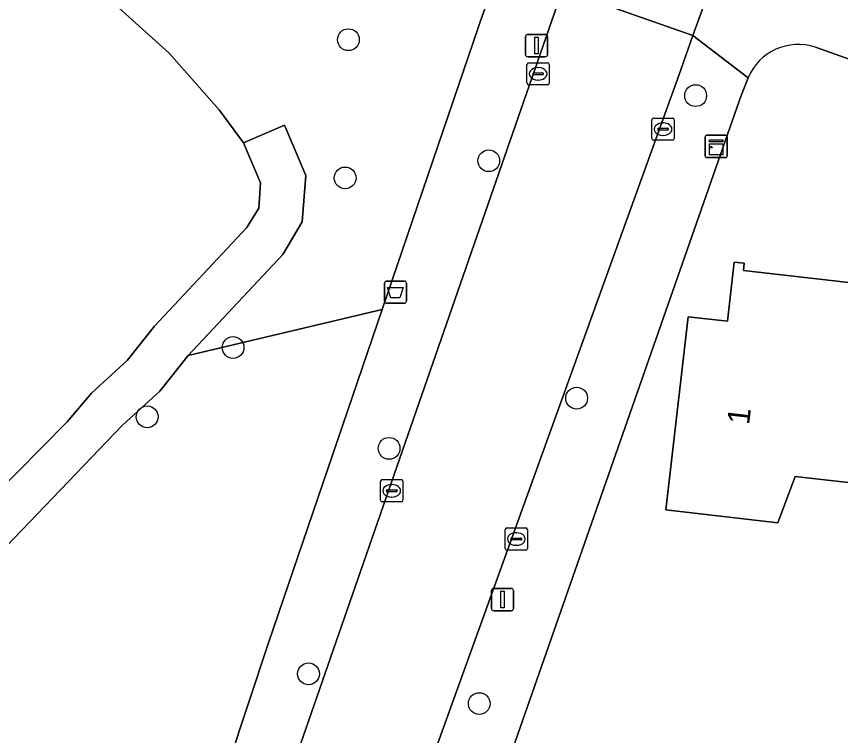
# Model space of a CAD drawing. Extents: x 162396 to 163643, y 386452 to 387406.
# Drawn here: x 162508.79 to 162545.79, y 386600.76 to 386633.03 of the extents above; entities that cross this region are included whole.
import ezdxf

# ---------------------------------------------------------------- set-up
doc = ezdxf.new("R2010")
doc.units = 0
for name, color, linetype in [('IMGEO_Afvalbak', 7, 'Continuous'), ('IMGEO_Boom', 7, 'Continuous'), ('IMGEO_Erf', 7, 'Continuous'), ('IMGEO_Groenvoorziening', 7, 'Continuous'), ('IMGEO_Kast', 7, 'Continuous'), ('IMGEO_Kolk', 7, 'Continuous'), ('IMGEO_Lichtmast', 7, 'Continuous'), ('IMGEO_Meer_plas_ven_vijver', 7, 'Continuous'), ('IMGEO_Oever', 7, 'Continuous'), ('IMGEO_Pand', 7, 'Continuous'), ('IMGEO_Pand_nummerreeks', 7, 'Continuous'), ('IMGEO_Rijbaan_lokaal_open', 7, 'Continuous'), ('IMGEO_Voetpad_open', 7, 'Continuous')]:
    doc.layers.add(name, color=color, linetype=linetype)

msp = doc.modelspace()

# ---------------------------------------------------------------- linework, layer by layer
at = {"layer": 'IMGEO_Afvalbak'}
for p, q in [((162525.313, 386620.259), (162525.313, 386621.059)), ((162525.313, 386621.059), (162525.313, 386620.259)), ((162525.413, 386621.159), (162526.203, 386621.159)), ((162526.203, 386621.159), (162525.413, 386621.159)), ((162526.303, 386621.059), (162526.303, 386620.259)), ((162526.303, 386620.259), (162526.303, 386621.059)), ((162526.203, 386620.159), (162525.413, 386620.159)), ((162525.413, 386620.159), (162526.203, 386620.159))]:
    msp.add_line(p, q, dxfattribs=at)
msp.add_lwpolyline([(162525.456, 386620.873), (162526.16, 386620.873), (162526.011, 386620.403), (162525.605, 386620.403), (162525.456, 386620.873)], dxfattribs=at)
for centre, start, end in [((162525.413, 386621.059), 90, 180), ((162525.413, 386621.059), 90, 180), ((162526.203, 386621.059), 0, 90), ((162526.203, 386621.059), 360, 90), ((162525.413, 386620.259), 180, 270), ((162525.413, 386620.259), 180, 270), ((162526.203, 386620.259), 270, 0), ((162526.203, 386620.259), 270, 0)]:
    msp.add_arc(centre, 0.1, start, end, dxfattribs=at)
at = {"layer": 'IMGEO_Boom'}
for centre in [(162523.697, 386631.991), (162539.287, 386629.479), (162529.999, 386626.557), (162523.549, 386625.786), (162518.519, 386618.177), (162533.945, 386615.901), (162514.663, 386615.062), (162525.522, 386613.648), (162521.907, 386603.527), (162529.572, 386602.192)]:
    msp.add_circle(centre, 0.489, dxfattribs=at)
at = {"layer": 'IMGEO_Erf'}
for points in [[(162549.244, 386630.03), (162544.673, 386631.651)], [(162541.641, 386630.284), (162541.368, 386629.555), (162541.261, 386629.271), (162530.664, 386598.974)], [(162546.932, 386612.025), (162543.754, 386612.39), (162542.976, 386610.303), (162537.948, 386610.882), (162538.946, 386619.555), (162540.717, 386619.352), (162541.022, 386622.009), (162541.47, 386621.958), (162541.433, 386621.633), (162547.731, 386620.908)]]:
    msp.add_lwpolyline(points, dxfattribs=at)
msp.add_arc((162543.898, 386629.324), 2.453, 71.5881, 156.9491, dxfattribs=at)
at = {"layer": 'IMGEO_Groenvoorziening'}
msp.add_lwpolyline([(162510.432, 386649.303), (162504.627, 386640.362), (162504.651, 386640.346), (162504.853, 386640.213), (162512.042, 386634.653), (162515.642, 386631.38), (162517.901, 386628.845), (162518.988, 386627.366), (162520.829, 386628.149), (162521.784, 386625.902), (162521.627, 386623.81), (162520.746, 386622.352), (162516.507, 386617.821), (162525.216, 386619.885), (162529.537, 386632.564), (162529.602, 386632.75), (162530.479, 386635.242), (162531.005, 386636.739)], dxfattribs=at)
msp.add_lwpolyline([(162525.216, 386619.885), (162516.507, 386617.821), (162515.233, 386616.222), (162513.55, 386614.693), (162506.937, 386607.814), (162505.589, 386606.205), (162502.385, 386602.764), (162503.519, 386602.191), (162507.651, 386600.102), (162517.104, 386595.322), (162518.289, 386599.414), (162520.116, 386604.921)], close=True, dxfattribs=at)
at = {"layer": 'IMGEO_Kast'}
for p, q in [((162539.709, 386626.774), (162539.709, 386627.615)), ((162539.709, 386627.615), (162539.709, 386626.774)), ((162539.784, 386627.699), (162540.625, 386627.699)), ((162540.625, 386627.699), (162539.784, 386627.699)), ((162540.709, 386627.624), (162540.709, 386626.783)), ((162540.709, 386626.783), (162540.709, 386627.624)), ((162540.634, 386626.699), (162539.793, 386626.699)), ((162539.793, 386626.699), (162540.634, 386626.699))]:
    msp.add_line(p, q, dxfattribs=at)
for points in [[(162539.904, 386627.489), (162540.504, 386627.489), (162540.504, 386627.404), (162539.904, 386627.404), (162539.904, 386627.489)], [(162539.904, 386627.314), (162540.504, 386627.314), (162540.504, 386626.825), (162539.904, 386626.825), (162539.904, 386627.314)]]:
    msp.add_lwpolyline(points, dxfattribs=at)
msp.add_circle((162539.988, 386627.163), 0.0377, dxfattribs=at)
for centre, start, end in [((162539.787, 386627.621), 92.4484, 184.2845), ((162539.787, 386627.621), 92.4484, 184.2845), ((162540.631, 386627.621), 2.4484, 94.2845), ((162540.631, 386627.621), 2.4484, 94.2845), ((162539.787, 386626.777), 182.4484, 274.2845), ((162539.787, 386626.777), 182.4484, 274.2845), ((162540.631, 386626.777), 272.4484, 4.2845), ((162540.631, 386626.777), 272.4484, 4.2845)]:
    msp.add_arc(centre, 0.0779, start, end, dxfattribs=at)
at = {"layer": 'IMGEO_Kolk'}
for p, q in [((162531.715, 386630.032), (162531.715, 386630.884)), ((162531.79, 386630.958), (162532.642, 386630.958)), ((162532.203, 386630.738), (162532.228, 386630.738)), ((162532.716, 386630.884), (162532.716, 386630.032)), ((162531.974, 386630.452), (162531.974, 386630.464)), ((162532.412, 386630.415), (162532.014, 386630.415)), ((162532.017, 386630.501), (162532.415, 386630.501)), ((162532.458, 386630.464), (162532.458, 386630.452)), ((162532.642, 386629.958), (162531.79, 386629.958)), ((162532.226, 386630.178), (162532.201, 386630.178)), ((162537.398, 386628.475), (162538.25, 386628.475)), ((162537.323, 386627.549), (162537.323, 386628.401)), ((162537.811, 386628.255), (162537.836, 386628.255)), ((162538.324, 386628.401), (162538.324, 386627.549)), ((162537.582, 386627.969), (162537.582, 386627.981)), ((162538.02, 386627.932), (162537.622, 386627.932)), ((162537.625, 386628.018), (162538.023, 386628.018)), ((162538.066, 386627.981), (162538.066, 386627.969)), ((162538.25, 386627.475), (162537.398, 386627.475)), ((162537.834, 386627.695), (162537.809, 386627.695)), ((162525.216, 386612.244), (162526.068, 386612.244)), ((162525.141, 386611.318), (162525.141, 386612.17)), ((162525.629, 386612.024), (162525.654, 386612.024)), ((162526.142, 386612.17), (162526.142, 386611.318)), ((162525.4, 386611.738), (162525.4, 386611.75)), ((162525.838, 386611.701), (162525.44, 386611.701)), ((162525.443, 386611.787), (162525.841, 386611.787)), ((162525.652, 386611.464), (162525.627, 386611.464)), ((162525.884, 386611.75), (162525.884, 386611.738)), ((162526.068, 386611.244), (162525.216, 386611.244)), ((162530.735, 386609.153), (162530.735, 386610.005)), ((162530.81, 386610.079), (162531.662, 386610.079)), ((162531.736, 386610.005), (162531.736, 386609.153)), ((162530.994, 386609.573), (162530.994, 386609.585)), ((162531.037, 386609.622), (162531.435, 386609.622)), ((162531.223, 386609.859), (162531.248, 386609.859)), ((162531.478, 386609.585), (162531.478, 386609.573)), ((162531.432, 386609.536), (162531.034, 386609.536)), ((162531.246, 386609.299), (162531.221, 386609.299)), ((162531.662, 386609.079), (162530.81, 386609.079))]:
    msp.add_line(p, q, dxfattribs=at)
for points in [[(162531.715, 386630.032), (162531.715, 386630.884)], [(162531.79, 386630.958), (162532.642, 386630.958)], [(162532.716, 386630.884), (162532.716, 386630.032)], [(162532.642, 386629.958), (162531.79, 386629.958)], [(162537.398, 386628.475), (162538.25, 386628.475)], [(162537.323, 386627.549), (162537.323, 386628.401)], [(162538.324, 386628.401), (162538.324, 386627.549)], [(162538.25, 386627.475), (162537.398, 386627.475)], [(162525.216, 386612.244), (162526.068, 386612.244)], [(162525.141, 386611.318), (162525.141, 386612.17)], [(162526.142, 386612.17), (162526.142, 386611.318)], [(162526.068, 386611.244), (162525.216, 386611.244)], [(162530.735, 386609.153), (162530.735, 386610.005)], [(162530.81, 386610.079), (162531.662, 386610.079)], [(162531.736, 386610.005), (162531.736, 386609.153)], [(162531.662, 386609.079), (162530.81, 386609.079)]]:
    msp.add_lwpolyline(points, dxfattribs=at)
for centre, radius, start, end in [((162531.792, 386630.882), 0.0765, 91.552, 178.448), ((162531.792, 386630.882), 0.0765, 91.552, 178.448), ((162532.64, 386630.882), 0.0765, 1.552, 88.448), ((162532.64, 386630.882), 0.0765, 1.552, 88.448), ((162532.014, 386630.461), 0.0403, 85.8775, 175.7526), ((162532.011, 386630.451), 0.0366, 178.938, 274.7102), ((162532.415, 386630.458), 0.043, 264.8664, 352.4533), ((162532.419, 386630.463), 0.0386, 1.7309, 96.639), ((162531.792, 386630.034), 0.0765, 181.552, 268.448), ((162531.792, 386630.034), 0.0765, 181.552, 268.448), ((162532.64, 386630.034), 0.0765, 271.552, 358.448), ((162532.64, 386630.034), 0.0765, 271.552, 358.448), ((162537.4, 386628.399), 0.0765, 91.552, 178.448), ((162537.4, 386628.399), 0.0765, 91.552, 178.448), ((162538.248, 386628.399), 0.0765, 1.552, 88.448), ((162538.248, 386628.399), 0.0765, 1.552, 88.448), ((162537.622, 386627.978), 0.0403, 85.8775, 175.7526), ((162537.619, 386627.968), 0.0366, 178.938, 274.7102), ((162538.023, 386627.975), 0.043, 264.8664, 352.4533), ((162538.027, 386627.98), 0.0386, 1.7309, 96.639), ((162537.4, 386627.551), 0.0765, 181.552, 268.448), ((162537.4, 386627.551), 0.0765, 181.552, 268.448), ((162538.248, 386627.551), 0.0765, 271.552, 358.448), ((162538.248, 386627.551), 0.0765, 271.552, 358.448), ((162525.218, 386612.168), 0.0765, 91.552, 178.448), ((162525.218, 386612.168), 0.0765, 91.552, 178.448), ((162526.066, 386612.168), 0.0765, 1.552, 88.448), ((162526.066, 386612.168), 0.0765, 1.552, 88.448), ((162525.44, 386611.747), 0.0403, 85.8775, 175.7526), ((162525.437, 386611.737), 0.0366, 178.938, 274.7102), ((162525.841, 386611.744), 0.043, 264.8664, 352.4533), ((162525.845, 386611.749), 0.0386, 1.7309, 96.639), ((162525.218, 386611.32), 0.0765, 181.552, 268.448), ((162525.218, 386611.32), 0.0765, 181.552, 268.448), ((162526.066, 386611.32), 0.0765, 271.552, 358.448), ((162526.066, 386611.32), 0.0765, 271.552, 358.448), ((162530.812, 386610.003), 0.0765, 91.552, 178.448), ((162530.812, 386610.003), 0.0765, 91.552, 178.448), ((162531.66, 386610.003), 0.0765, 1.552, 88.448), ((162531.66, 386610.003), 0.0765, 1.552, 88.448), ((162531.034, 386609.582), 0.0403, 85.8775, 175.7526), ((162531.439, 386609.584), 0.0386, 1.7309, 96.639), ((162531.031, 386609.572), 0.0366, 178.938, 274.7102), ((162531.435, 386609.579), 0.043, 264.8664, 352.4533), ((162530.812, 386609.155), 0.0765, 181.552, 268.448), ((162530.812, 386609.155), 0.0765, 181.552, 268.448), ((162531.66, 386609.155), 0.0765, 271.552, 358.448), ((162531.66, 386609.155), 0.0765, 271.552, 358.448)]:
    msp.add_arc(centre, radius, start, end, dxfattribs=at)
for centre, major_axis, ratio, start_param, end_param in [((162532.202, 386630.458), (-0.387, 0.002), 0.722429, 4.712389, 7.853982), ((162532.227, 386630.458), (-0.39, 0.002), 0.717154, 1.570796, 4.712389), ((162537.81, 386627.975), (-0.387, 0.002), 0.722429, 4.712389, 7.853982), ((162537.835, 386627.975), (-0.39, 0.002), 0.717154, 1.570796, 4.712389), ((162525.628, 386611.744), (-0.387, 0.002), 0.722429, 4.712389, 7.853982), ((162525.653, 386611.744), (-0.39, 0.002), 0.717154, 1.570796, 4.712389), ((162531.222, 386609.579), (-0.387, 0.002), 0.722429, 4.712389, 7.853982), ((162531.247, 386609.579), (-0.39, 0.002), 0.717154, 1.570796, 4.712389)]:
    msp.add_ellipse(centre, major_axis=major_axis, ratio=ratio, start_param=start_param, end_param=end_param, dxfattribs=at)
at = {"layer": 'IMGEO_Lichtmast'}
for p, q in [((162531.747, 386632.226), (162532.537, 386632.226)), ((162532.537, 386632.226), (162531.747, 386632.226)), ((162531.647, 386631.326), (162531.647, 386632.126)), ((162531.647, 386632.126), (162531.647, 386631.326)), ((162532.637, 386632.126), (162532.637, 386631.326)), ((162532.637, 386631.326), (162532.637, 386632.126)), ((162532.537, 386631.226), (162531.747, 386631.226)), ((162531.747, 386631.226), (162532.537, 386631.226)), ((162530.119, 386606.462), (162530.119, 386607.262)), ((162530.119, 386607.262), (162530.119, 386606.462)), ((162530.219, 386607.362), (162531.009, 386607.362)), ((162531.009, 386607.362), (162530.219, 386607.362)), ((162531.109, 386607.262), (162531.109, 386606.462)), ((162531.109, 386606.462), (162531.109, 386607.262)), ((162531.009, 386606.362), (162530.219, 386606.362)), ((162530.219, 386606.362), (162531.009, 386606.362))]:
    msp.add_line(p, q, dxfattribs=at)
for points in [[(162532.067, 386632.101), (162532.217, 386632.101), (162532.217, 386631.351), (162532.067, 386631.351), (162532.067, 386632.101)], [(162530.539, 386607.237), (162530.689, 386607.237), (162530.689, 386606.487), (162530.539, 386606.487), (162530.539, 386607.237)]]:
    msp.add_lwpolyline(points, dxfattribs=at)
for centre, start, end in [((162531.747, 386632.126), 90, 180), ((162531.747, 386632.126), 90, 180), ((162532.537, 386632.126), 0, 90), ((162532.537, 386632.126), 360, 90), ((162531.747, 386631.326), 180, 270), ((162531.747, 386631.326), 180, 270), ((162532.537, 386631.326), 270, 0), ((162532.537, 386631.326), 270, 0), ((162530.219, 386607.262), 90, 180), ((162530.219, 386607.262), 90, 180), ((162531.009, 386607.262), 0, 90), ((162531.009, 386607.262), 360, 90), ((162530.219, 386606.462), 180, 270), ((162530.219, 386606.462), 180, 270), ((162531.009, 386606.462), 270, 0), ((162531.009, 386606.462), 270, 0)]:
    msp.add_arc(centre, 0.1, start, end, dxfattribs=at)
at = {"layer": 'IMGEO_Meer_plas_ven_vijver'}
msp.add_lwpolyline([(162505.448, 386609.151), (162511.077, 386614.836), (162512.155, 386616.128), (162513.769, 386617.594), (162514.992, 386619.129), (162519.142, 386623.565), (162519.668, 386624.436), (162519.753, 386625.567), (162518.988, 386627.366), (162517.901, 386628.845), (162515.642, 386631.38), (162512.042, 386634.653), (162504.853, 386640.213)], dxfattribs=at)
at = {"layer": 'IMGEO_Oever'}
msp.add_lwpolyline([(162506.937, 386607.814), (162513.55, 386614.693), (162515.233, 386616.222), (162516.507, 386617.821), (162520.746, 386622.352), (162521.627, 386623.81), (162521.784, 386625.902), (162520.829, 386628.149), (162518.988, 386627.366), (162519.753, 386625.567), (162519.668, 386624.436), (162519.142, 386623.565), (162514.992, 386619.129), (162513.769, 386617.594), (162512.155, 386616.128), (162511.077, 386614.836), (162505.448, 386609.151)], dxfattribs=at)
at = {"layer": 'IMGEO_Pand'}
msp.add_lwpolyline([(162548.132, 386621.179), (162547.767, 386621.221), (162547.731, 386620.908), (162541.433, 386621.633), (162541.47, 386621.958), (162541.022, 386622.009), (162540.717, 386619.352), (162538.946, 386619.555), (162537.948, 386610.882), (162542.976, 386610.303), (162543.754, 386612.39), (162546.932, 386612.025)], close=True, dxfattribs=at)
at = {"layer": 'IMGEO_Rijbaan_lokaal_open'}
for points in [[(162533.684, 386635.22), (162533.31, 386634.243), (162539.168, 386632.177), (162540.018, 386634.532)], [(162538.542, 386630.425), (162538.637, 386630.689), (162539.168, 386632.177), (162533.31, 386634.243), (162520.916, 386598.567), (162519.409, 386592.958), (162517.768, 386586.008), (162516.873, 386578.96), (162512.175, 386536.978), (162510.746, 386524.31), (162509.296, 386510.744)], [(162515.091, 386509.886), (162518.171, 386537.265), (162519.073, 386545.782), (162523.205, 386581.894), (162523.891, 386586.28), (162524.764, 386590.188), (162526.069, 386595.297), (162527.576, 386600.04), (162538.542, 386630.425)]]:
    msp.add_lwpolyline(points, dxfattribs=at)
at = {"layer": 'IMGEO_Voetpad_open'}
msp.add_lwpolyline([(162516.873, 386578.96), (162517.768, 386586.008), (162519.409, 386592.958), (162520.916, 386598.567), (162533.31, 386634.243), (162530.479, 386635.242), (162529.602, 386632.75), (162529.537, 386632.564), (162525.216, 386619.885), (162520.116, 386604.921), (162518.289, 386599.414), (162517.104, 386595.322), (162516.634, 386593.698), (162515.418, 386587.914), (162515.018, 386587.956), (162513.322, 386572.875), (162511.659, 386558.094), (162511.642, 386557.939), (162509.967, 386543.053), (162509.928, 386542.705), (162509.288, 386537.015), (162511.213, 386537.082), (162512.175, 386536.978)], close=True, dxfattribs=at)
for points in [[(162540.018, 386634.532), (162539.168, 386632.177), (162541.641, 386630.284)], [(162526.67, 386582.569), (162527.699, 386588.467), (162529.53, 386595.31), (162530.664, 386598.974), (162541.261, 386629.271), (162541.368, 386629.555), (162541.641, 386630.284), (162539.168, 386632.177), (162538.637, 386630.689), (162538.542, 386630.425), (162527.576, 386600.04), (162528.05, 386599.883), (162526.543, 386595.14), (162526.069, 386595.297), (162524.764, 386590.188), (162525.256, 386590.1), (162523.697, 386581.806), (162523.205, 386581.894), (162519.073, 386545.782), (162519.531, 386545.731), (162518.635, 386537.214), (162518.171, 386537.265), (162515.091, 386509.886)], [(162544.673, 386631.651), (162549.244, 386630.03), (162549.421, 386629.967), (162572.362, 386621.897), (162573.621, 386621.455), (162596.17, 386613.523), (162596.286, 386613.509), (162604.405, 386610.482), (162604.476, 386610.426), (162627.944, 386602.131), (162628.867, 386601.804), (162650.661, 386594.101), (162655.686, 386592.692), (162655.827, 386594.677)]]:
    msp.add_lwpolyline(points, dxfattribs=at)
msp.add_arc((162543.898, 386629.324), 2.453, 71.5881, 156.9491, dxfattribs=at)

# ---------------------------------------------------------------- texts
at = {"layer": 'IMGEO_Pand_nummerreeks'}
msp.add_text('1', height=1, rotation=83.4359, dxfattribs=at).set_placement((162541.687, 386614.683))

doc.saveas('drawing.dxf')
